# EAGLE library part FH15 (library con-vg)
CONNECTOR female, 15 pins, type H, rows DZ
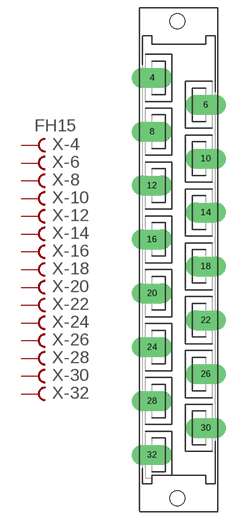
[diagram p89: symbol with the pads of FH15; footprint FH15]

Designator prefix X; gates -4=FVAL -6=FEM -8=FEM -10=FEM -12=FEM -14=FEM -16=FEM -18=FEM -20=FEM -22=FEM -24=FEM -26=FEM -28=FEM -30=FEM -32=FEM

## FH15  [FH15]
4  -4:B  pas
6  -6:B  pas
8  -8:B  pas
10  -10:B  pas
12  -12:B  pas
14  -14:B  pas
16  -16:B  pas
18  -18:B  pas
20  -20:B  pas
22  -22:B  pas
24  -24:B  pas
26  -26:B  pas
28  -28:B  pas
30  -30:B  pas
32  -32:B  pas

## Footprint FH15 (pad centres in mm)
CONNECTOR female, 15 pins, type H, rows DZ
drill 1.676 pad 3.81 long: 4 -5.08,34.315; 6 5.08,29.235; 8 -5.08,24.155; 10 5.08,19.075; 12 -5.08,13.995; 14 5.08,8.915; 16 -5.08,3.835; 18 5.08,-1.245; 20 -5.08,-6.325; 22 5.08,-11.405; 24 -5.08,-16.485; 26 5.08,-21.565; 28 -5.08,-26.645; 30 5.08,-31.725; 32 -5.08,-36.805
hole 2.794 at -0.305,44.983
hole 2.794 at -0.305,-44.983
